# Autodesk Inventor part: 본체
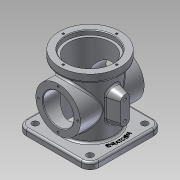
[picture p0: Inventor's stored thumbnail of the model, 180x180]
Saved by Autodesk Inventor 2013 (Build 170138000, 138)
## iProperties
Created: 2021-03
Part Number: 본체
Material: 알루미늄 6061
Document SubType Name: Modeling
Designer: hana-cad24
Density: 2.71 g/cm^3
Mass: 823.106 g
Surface Area: 857.016 cm^2
Volume: 303.729 cm^3
Author: hana-cad24
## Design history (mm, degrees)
sketch "스케치1"
  geometry: L1 (-57, -57)-(57, -57); L2 (57, -57)-(57, 57); L3 (57, 57)-(-57, 57); L4 (-57, 57)-(-57, -57); L5 (-57, -57)-(57, 57); L6 (57, -57)-(-57, 57); 1 further point
  constraints: 12 end point, 2 midpoint, 2 parallel, 1 horizontal, 1 perpendicular
  dimensions: "d0" = 114 distance of L3.end L2.end; "d1" = 114 distance of L2.end L1.end
extrude "돌출1" new body sketch "스케치1" distance "d2" = 10; taper "d3" = 0 deg
fillet "모깎기1" dims "d4" = 14
sketch "스케치2"
  geometry: A1 r 14 centre (43, 43) between (57, 43) and (43, 57) reference; A2 r 14 centre (-43, 43) between (-43, 57) and (-57, 43) reference; A3 r 14 centre (-43, -43) between (-57, -43) and (-43, -57) reference; A4 r 14 centre (43, -43) between (43, -57) and (57, -43) reference; 1 further point
hole "구멍1" sketch "스케치2" at (-43, 43), (43, 43), (43, -43), (-43, -43) diameter "d5" = 10; stored, may be unused: countersink angle "d9" = 90 deg, drill point angle "d11" = 118 deg; dims "d6" = 6, "d7" = 4, "d8" = 2, "d10" = 8
sketch "스케치4"
  geometry: C1 r 38 at (0, 0); 1 further point
  constraints: 1 centre point, 1 coincident
  dimensions: "d13" = 76 diameter of C1
extrude "돌출2" join sketch "스케치4" distance "d14" = 88; taper "d15" = 0 deg
sketch "스케치5"
  geometry: C1 r 38 at (0, 0) reference; C2 r 48 at (0, 0)
  constraints: 1 centre point, 1 coincident
  dimensions: "d16" = 96 diameter of C2
extrude "돌출3" join sketch "스케치5" distance "d17" = 13; taper "d18" = 0 deg
sketch "스케치6"
  geometry: C1 r 48 at (0, 0) reference
hole "구멍2" sketch "스케치6" at (0, 0) diameter "d19" = 66; stored, may be unused: countersink angle "d23" = 90 deg, drill point angle "d25" = 118 deg; dims "d20" = 6, "d21" = 74, "d22" = 7, "d24" = 8
sketch "스케치7"
  geometry: L1 (48, 98)-(38, 98) reference; L2 (38, 98)-(38, 10) reference; L3 (38, 10)-(57, 10) reference; L4 (57, 10)-(57, 0) reference; L5 (57, 0)-(33, 0) reference; L6 (33, 0)-(33, 104) reference; L7 (33, 104)-(37, 104) reference; L8 (37, 104)-(37, 111) reference; L9 (37, 111)-(48, 111) reference; L10 (48, 111)-(48, 98) reference; L11 (-38, 98)-(-48, 98) reference; L12 (-48, 98)-(-48, 111) reference; L13 (-48, 111)-(-37, 111) reference; L14 (-37, 111)-(-37, 104) reference; L15 (-37, 104)-(-33, 104) reference; L16 (-33, 104)-(-33, 0) reference; L17 (-33, 0)-(-57, 0) reference; L18 (-57, 0)-(-57, 10) reference; L19 (-57, 10)-(-38, 10) reference; L20 (-38, 10)-(-38, 98) reference; L21 (-50, 89)-(50, 89); L22 (50, 89)-(50, 54); L23 (50, 54)-(-50, 54); L24 (-50, 54)-(-50, 89); 2 further points
  constraints: 8 end point, 2 parallel, 1 horizontal, 1 midpoint, 1 perpendicular, 1 vertical alignment
  dimensions: "d26" = 54 distance from line of point (0, 0) L23; "d27" = 100 distance of L21.start L21.end; "d28" = 70 diameter of L21 L23
revolve "회전1" sketch "스케치7" stored, may be unused: angle "d29" = 90 deg
sketch "스케치8"
  geometry: C1 r 35 at (0, 0) reference; C2 r 24 at (0, 0); 1 further point
  constraints: 1 centre point, 1 coincident
  dimensions: "d30" = 48 diameter of C2
extrude "돌출4" cut sketch "스케치8" stored distance "d31" = 13; taper "d32" = 0 deg
sketch "스케치9"
  geometry: C1 r 33 at (0, 0) reference
extrude "돌출5" cut sketch "스케치9" stored distance "d33" = 13; taper "d34" = 0 deg
sketch "스케치10"
  geometry: C1 r 24 at (0, 0) reference; 2 further points
  constraints: 1 vertical alignment
  dimensions: "d35" = 31 distance of point (0, 31) C1.centre
hole "구멍3" sketch "스케치10" at (0, 31) diameter "d36" = 3.242; stored, may be unused: countersink angle "d40" = 90 deg, drill point angle "d42" = 118 deg; dims "d37" = 6, "d38" = 74, "d39" = 7, "d41" = 8
sketch "스케치11"
  geometry: C1 r 37 at (0, 0) reference; 1 further point
  constraints: 1 horizontal alignment
  dimensions: "d46" = 42 distance of C1.centre point (42, 0)
hole "구멍4" sketch "스케치11" at (42, 0) diameter "d47" = 3.242; stored, may be unused: countersink angle "d51" = 90 deg, drill point angle "d53" = 118 deg; dims "d48" = 6, "d49" = 74, "d50" = 7, "d52" = 8
node "작업 평면1"
sketch "스케치12"
  geometry: L1 (-50, 19)-(-50, 89) reference; L2 (50, 19)-(50, 89) reference; L3 (-38, 10)-(38, 10) reference; L4 (-7, 41)-(-7, 70); L5 (7, 41)-(7, 70); L6 (48, 111)-(-48, 111) reference; A1 r 7 centre (0, 41) between (-7, 41) and (7, 41); A2 r 7 centre (0, 70) between (7, 70) and (-7, 70); 3 further points
  constraints: 4 end point, 4 point on circle, 3 tangent, 2 centre point, 2 midpoint, 1 parallel, 1 perpendicular, 1 vertical alignment
  dimensions: "d61" = 14 distance between parallel lines of L4 L5; "d65" = 7 radius of A1; "d68" = 43 dimension on A1 A2; "d69" = 13 vertical distance of A1.centre point (-50, 54)
extrude "돌출6" join sketch "스케치12" stored distance "d70" = 13; taper "d71" = 0 deg
feature "면 기울기1" dims angle "d72" = 15 deg
sketch "스케치13"
  geometry: A1 r 7 centre (0, -41) between (7, -41) and (-7, -41) reference; A2 r 7 centre (0, -70) between (-7, -70) and (7, -70) reference; 1 further point
hole "구멍5" sketch "스케치13" at (0, -41), (0, -70) diameter "d73" = 4.134; stored, may be unused: countersink angle "d77" = 90 deg, drill point angle "d79" = 118 deg; dims "d74" = 8, "d75" = 74, "d76" = 7, "d78" = 10
node "작업 평면2"
sketch "스케치14"
  geometry: C1 r 50 at (0, 0); 1 further point
  constraints: 1 centre point, 1 coincident, 1 other
  dimensions: "d81" = 100 diameter of C1
feature "엠보싱1" sketch "스케치14" dims "d0" = 114, "d1" = 114, "d82" = 0.5, "d83" = 0
fillet "모깎기2" dims "d84" = 3
fillet "모깎기3" dims "d85" = 3
fillet "모깎기4" dims "d86" = 3
fillet "모깎기5" dims "d87" = 3
fillet "모깎기6" dims "d88" = 3
chamfer "모따기1" distance "d89" = 1; stored, may be unused: second distance "d90" = 2, angle "d91" = 45 deg
node "솔리드1"
pattern_circular "원형 패턴1" dims angle "d44" = 360 deg
mirror "대칭1"
pattern_circular "원형 패턴2" dims angle "d55" = 360 deg
node "절단 모서리 투영1"
other parameters: "d57" = 55, "d80" = 3
